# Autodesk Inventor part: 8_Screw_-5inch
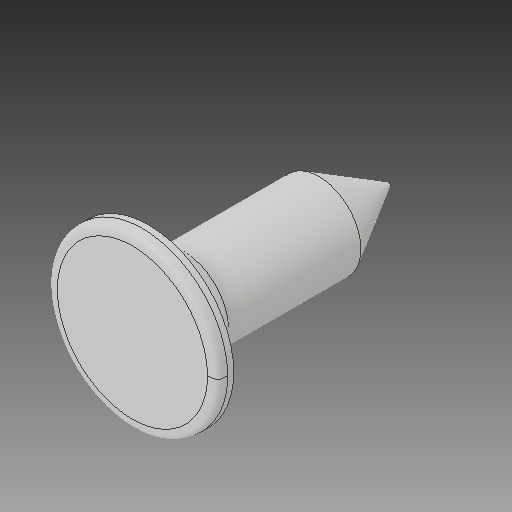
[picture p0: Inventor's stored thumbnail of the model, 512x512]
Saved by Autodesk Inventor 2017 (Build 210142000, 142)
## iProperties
Created: 2017-05
Part Number: 8_Screw_-5inch
Material: Generic
Document SubType Name: Modeling
Designer: Savy
Density: 1 g/cm^3
Appearance: Default
Mass: 0.209958 g
Surface Area: 2.4308 cm^2
Volume: 0.209958 cm^3
Author: Savy
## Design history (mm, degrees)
feature "SOLID1"
body "Solid1"
